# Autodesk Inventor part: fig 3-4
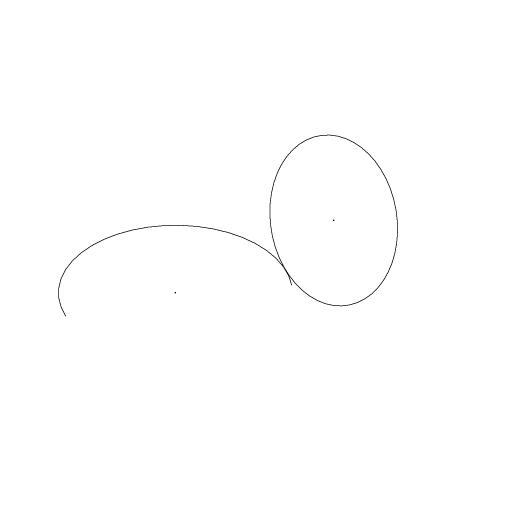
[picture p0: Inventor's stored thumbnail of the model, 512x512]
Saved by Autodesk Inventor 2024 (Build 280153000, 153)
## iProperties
Created: 2009-11
Part Number: fig 3-4
Document SubType Name: Modeling
Designer: Sham
Density: 1 g/cm^3
Material: Generic
Appearance: Default
Author: Sham
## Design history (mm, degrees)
sketch "Sketch1"
  geometry: A1 r 10.623 centre (-1.113, -21.203) between (5.463, -12.861) and (-5.537, -30.861); 1 further point; 1 other entity
  constraints: 2 point on circle, 1 centre point, 4 other
